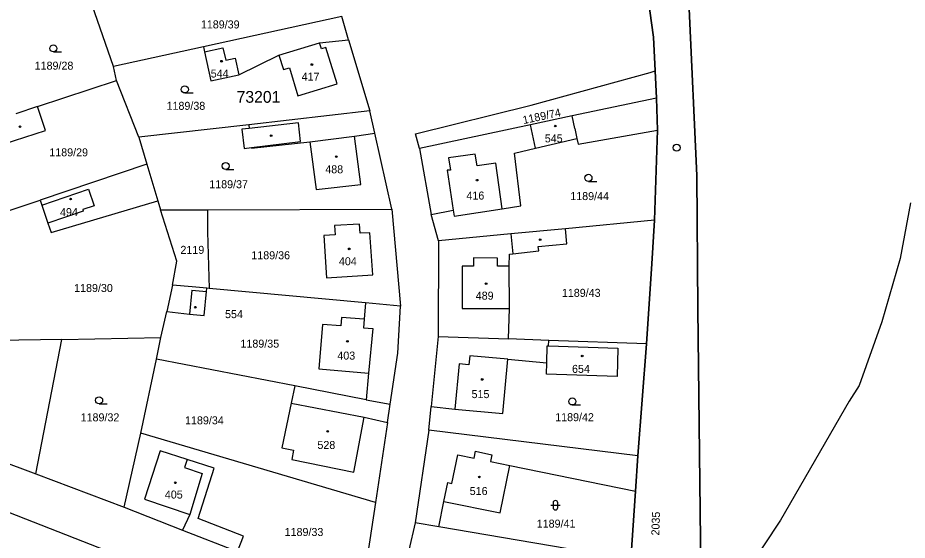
# Model space of a CAD drawing. Extents: x -794765 to -785424, y -1118958 to -1108731.
# Drawn here: x -787839.7 to -787650.9, y -1116620.6 to -1116509.6 of the extents above; entities that cross this region are included whole.
import ezdxf

# ---------------------------------------------------------------- set-up
doc = ezdxf.new("R2010")
doc.units = 0
for name, color, linetype in [('Level 66', 7, 'Continuous'), ('Level 75', 7, 'Continuous'), ('Level 76', 7, 'Continuous'), ('Level 77', 7, 'Continuous'), ('Level 79', 7, 'Continuous'), ('Level 81', 7, 'Continuous'), ('Vrstva 1', 7, 'Continuous'), ('Vrstva 55', 7, 'Continuous')]:
    doc.layers.add(name, color=color, linetype=linetype)

msp = doc.modelspace()

# ---------------------------------------------------------------- linework, layer by layer
at = {"layer": 'Level 66'}
for p, q in [((-787832.14, -1116516.88), (-787830.39, -1116516.88)), ((-787804.24, -1116525.6), (-787802.49, -1116525.6)), ((-787795.56, -1116541.86), (-787793.81, -1116541.86)), ((-787718.55, -1116544.38), (-787716.8, -1116544.38)), ((-787822.44, -1116591.63), (-787820.69, -1116591.63)), ((-787721.98, -1116591.87), (-787720.23, -1116591.87)), ((-787726.55, -1116613.16), (-787724.55, -1116613.16)), ((-787726.05, -1116612.66), (-787726.05, -1116613.66)), ((-787725.05, -1116613.66), (-787725.05, -1116612.66))]:
    msp.add_line(p, q, dxfattribs=at)
for centre in [(-787832.14, -1116516.13), (-787804.24, -1116524.85), (-787795.56, -1116541.11), (-787718.55, -1116543.63), (-787822.44, -1116590.88), (-787721.98, -1116591.12)]:
    msp.add_circle(centre, 0.75, dxfattribs=at)
for centre, start, end in [((-787725.55, -1116612.66), 0, 180), ((-787725.55, -1116613.66), 180, 359.9879)]:
    msp.add_arc(centre, 0.5, start, end, dxfattribs=at)
at = {"layer": 'Level 75'}
for p, q in [((-787819.38, -1116520), (-787824.68, -1116504.6)), ((-787770.94, -1116509.39), (-787800.27, -1116515.81)), ((-787769.46, -1116514.31), (-787770.94, -1116509.39)), ((-787769.46, -1116514.31), (-787764.94, -1116529.41)), ((-787800.27, -1116515.81), (-787819.38, -1116520)), ((-787800.27, -1116515.81), (-787800.05, -1116516.84)), ((-787818.75, -1116522.97), (-787819.38, -1116520)), ((-787705.48, -1116521.22), (-787704.38, -1116520.92)), ((-787704.38, -1116520.92), (-787704.1, -1116526.68)), ((-787835.52, -1116528.5), (-787818.75, -1116522.97)), ((-787814.01, -1116535.01), (-787818.75, -1116522.97)), ((-787704.1, -1116526.68), (-787703.91, -1116533.48)), ((-787835.52, -1116528.5), (-787840.15, -1116530.03)), ((-787764.94, -1116529.41), (-787790.66, -1116532.35)), ((-787763.9, -1116534.13), (-787764.94, -1116529.41)), ((-787790.66, -1116532.35), (-787814.01, -1116535.01)), ((-787730.84, -1116532.35), (-787754.45, -1116537.36)), ((-787729.78, -1116537.32), (-787730.84, -1116532.35)), ((-787760.31, -1116550.28), (-787763.9, -1116534.13)), ((-787754.45, -1116537.36), (-787755.27, -1116534.26)), ((-787703.91, -1116533.48), (-787704.56, -1116552.61)), ((-787814.01, -1116535.01), (-787812.3, -1116540.72)), ((-787754.45, -1116537.36), (-787751.94, -1116551.42)), ((-787812.3, -1116540.72), (-787834.94, -1116548.37)), ((-787812.3, -1116540.72), (-787809.97, -1116548.49)), ((-787842.6, -1116550.95), (-787834.94, -1116548.37)), ((-787809.97, -1116548.49), (-787809.38, -1116550.45)), ((-787809.38, -1116550.45), (-787799.45, -1116550.42)), ((-787799.45, -1116550.42), (-787760.31, -1116550.28)), ((-787760.31, -1116550.28), (-787758.43, -1116570.89)), ((-787750.4, -1116557.03), (-787751.94, -1116551.42)), ((-787704.56, -1116552.61), (-787723.43, -1116554.43)), ((-787750.4, -1116557.03), (-787750.49, -1116577.34)), ((-787806.86, -1116566.41), (-787808.09, -1116572.02)), ((-787799.07, -1116567.13), (-787799.56, -1116567.08)), ((-787765.88, -1116570.2), (-787799.07, -1116567.13)), ((-787758.43, -1116570.89), (-787765.88, -1116570.2)), ((-787809.3, -1116577.54), (-787808.09, -1116572.02)), ((-787830.33, -1116577.93), (-787809.3, -1116577.54)), ((-787810.27, -1116582.17), (-787809.3, -1116577.54)), ((-787750.49, -1116577.34), (-787751.96, -1116592.22)), ((-787750.49, -1116577.34), (-787735.49, -1116577.85)), ((-787830.33, -1116577.93), (-787859.23, -1116578.48)), ((-787835.9, -1116606.5), (-787830.33, -1116577.93)), ((-787726.99, -1116578.15), (-787735.49, -1116577.85)), ((-787727.03, -1116579.29), (-787726.99, -1116578.15)), ((-787706.23, -1116578.86), (-787726.99, -1116578.15)), ((-787706.23, -1116578.86), (-787708.05, -1116602.7)), ((-787813.56, -1116597.87), (-787810.27, -1116582.17)), ((-787780.89, -1116587.83), (-787810.27, -1116582.17)), ((-787765.71, -1116590.76), (-787780.89, -1116587.83)), ((-787765.71, -1116590.76), (-787760.64, -1116591.73)), ((-787761.22, -1116595.59), (-787760.64, -1116591.73)), ((-787752.45, -1116597.2), (-787751.96, -1116592.22)), ((-787761.22, -1116595.59), (-787763.76, -1116612.56)), ((-787860.7, -1116597.13), (-787835.9, -1116606.5)), ((-787817.13, -1116613.58), (-787813.56, -1116597.87)), ((-787763.76, -1116612.56), (-787813.56, -1116597.87)), ((-787752.45, -1116597.2), (-787755.32, -1116616.93)), ((-787708.05, -1116602.7), (-787752.45, -1116597.2)), ((-787708.05, -1116602.7), (-787708.57, -1116610.15)), ((-787835.9, -1116606.5), (-787817.13, -1116613.58)), ((-787708.57, -1116610.15), (-787709.58, -1116624.69)), ((-787817.13, -1116613.58), (-787804.7, -1116618.43)), ((-787813.81, -1116625.56), (-787841.59, -1116614.67)), ((-787755.32, -1116616.93), (-787756.71, -1116622.71)), ((-787750.28, -1116617.78), (-787755.32, -1116616.93)), ((-787804.7, -1116618.43), (-787793.06, -1116622.97)), ((-787709.58, -1116624.69), (-787750.28, -1116617.78))]:
    msp.add_line(p, q, dxfattribs=at)
for points in [[(-787693.98, -1116663.52), (-787691.68, -1116661.08), (-787693.44, -1116656.57), (-787695.13, -1116646.88), (-787694.77, -1116620.61), (-787695.36, -1116571.42), (-787695.53, -1116543.16), (-787697.17, -1116507.73), (-787699.35, -1116491.37), (-787704.1, -1116471.95), (-787713.77, -1116444.97), (-787730.07, -1116413.4), (-787748.85, -1116386.9), (-787769.63, -1116365.02), (-787796.66, -1116346.09)], [(-787809.33, -1116349.7), (-787801.57, -1116354.26), (-787773.08, -1116375.71), (-787754.69, -1116394.98), (-787740.05, -1116414.46), (-787723.7, -1116441.75), (-787713.22, -1116470.7), (-787707.44, -1116494.38), (-787704.74, -1116513.73), (-787704.38, -1116520.92)], [(-787792.79, -1116521.76), (-787784.26, -1116517.54), (-787783.32, -1116520.65), (-787782.02, -1116520.26), (-787780.23, -1116526.19), (-787771.91, -1116523.69), (-787774.28, -1116515.93), (-787775.23, -1116516.22), (-787775.62, -1116514.93), (-787769.46, -1116514.31)], [(-787800.05, -1116516.84), (-787796.14, -1116515.98), (-787795.55, -1116518.64), (-787793.57, -1116518.2), (-787792.79, -1116521.76)], [(-787800.05, -1116516.84), (-787798.69, -1116523.02), (-787792.79, -1116521.76)], [(-787755.27, -1116534.26), (-787730.74, -1116528.21), (-787705.48, -1116521.22)], [(-787704.1, -1116526.68), (-787722.02, -1116530.48), (-787730.84, -1116532.35)], [(-787844.57, -1116551.62), (-787845.98, -1116547.55), (-787848.96, -1116538.74), (-787842.56, -1116536.39), (-787833.85, -1116533.56), (-787835.52, -1116528.5)], [(-787790.66, -1116532.35), (-787790.57, -1116533.12), (-787792.14, -1116533.29), (-787791.67, -1116537.39), (-787790.11, -1116537.21), (-787790.09, -1116537.35), (-787777.71, -1116535.98), (-787776.37, -1116546.13), (-787766.9, -1116545.04), (-787768.19, -1116534.8), (-787763.9, -1116534.13)], [(-787729.78, -1116537.32), (-787721.01, -1116535.26), (-787720.75, -1116536.47), (-787703.91, -1116533.48)], [(-787751.94, -1116551.42), (-787747.28, -1116550.47), (-787747.09, -1116551.78), (-787736.85, -1116550.2), (-787732.87, -1116549.58), (-787734.24, -1116538.36), (-787729.78, -1116537.32)], [(-787834.94, -1116548.37), (-787834.59, -1116549.42), (-787833.29, -1116553.25), (-787832.62, -1116555.23), (-787809.97, -1116548.49)], [(-787806.86, -1116566.41), (-787805.96, -1116561.31), (-787809.38, -1116550.45)], [(-787799.45, -1116550.42), (-787799.44, -1116551.72), (-787799.43, -1116555.12), (-787799.07, -1116567.13)], [(-787704.56, -1116552.61), (-787705.09, -1116561.9), (-787706.23, -1116578.86)], [(-787764.34, -1116564.26), (-787764.96, -1116555.28), (-787767.04, -1116555.41), (-787767.16, -1116553.44), (-787772.47, -1116553.72), (-787772.34, -1116555.7), (-787774.72, -1116555.86), (-787774.14, -1116564.87), (-787764.34, -1116564.26)], [(-787723.43, -1116554.43), (-787735.01, -1116555.55), (-787750.4, -1116557.03)], [(-787735.49, -1116577.85), (-787735.33, -1116571.39), (-787735.39, -1116562.39), (-787735.34, -1116559.83), (-787734.61, -1116559.75), (-787729.11, -1116559.14), (-787729.2, -1116558.2), (-787723.12, -1116557.61), (-787723.43, -1116554.43)], [(-787799.56, -1116567.08), (-787802.69, -1116566.8), (-787806.86, -1116566.41)], [(-787808.09, -1116572.02), (-787803.23, -1116572.59), (-787800.1, -1116572.86), (-787799.63, -1116567.76), (-787799.56, -1116567.08)], [(-787765.88, -1116570.2), (-787766.18, -1116573.66), (-787770.99, -1116573.27), (-787771.15, -1116575.07), (-787775, -1116574.77), (-787775.78, -1116584.21), (-787765.23, -1116585.13), (-787765.71, -1116590.76)], [(-787760.64, -1116591.73), (-787759.04, -1116580.87), (-787758.43, -1116570.89)], [(-787727.03, -1116579.29), (-787712.3, -1116579.8), (-787712.46, -1116585.85), (-787727.48, -1116585.32), (-787727.4, -1116582.93)], [(-787727.4, -1116582.93), (-787727.28, -1116579.29), (-787727.03, -1116579.29)], [(-787751.96, -1116592.22), (-787746.92, -1116592.74), (-787736.74, -1116593.67), (-787735.66, -1116582.13), (-787727.4, -1116582.93)], [(-787780.89, -1116587.83), (-787781.67, -1116591.48), (-787783.63, -1116600.98), (-787781.17, -1116601.44), (-787781.55, -1116603.47), (-787768.37, -1116606.13), (-787766.18, -1116594.49), (-787761.22, -1116595.59)], [(-787793.06, -1116622.97), (-787791.76, -1116619.74), (-787801.44, -1116615.95), (-787798.01, -1116605.31), (-787803.77, -1116603.44), (-787809.5, -1116601.59), (-787812.82, -1116611.87), (-787803.19, -1116615.15), (-787804.7, -1116618.43)], [(-787750.28, -1116617.78), (-787749.25, -1116612.35), (-787737.26, -1116614.78), (-787735.22, -1116604.69), (-787708.57, -1116610.15)], [(-787763.76, -1116612.56), (-787766.31, -1116629.36), (-787768.64, -1116631.43), (-787771.78, -1116631.26)]]:
    msp.add_lwpolyline(points, dxfattribs=at)
at = {"layer": 'Level 77'}
for p, q in [((-787784.26, -1116517.54), (-787775.62, -1116514.93)), ((-787721.46, -1116533.12), (-787722.02, -1116530.48)), ((-787780.12, -1116531.94), (-787790.57, -1116533.12)), ((-787779.66, -1116535.91), (-787780.12, -1116531.94)), ((-787721.46, -1116533.12), (-787721.01, -1116535.26)), ((-787790.11, -1116537.21), (-787779.66, -1116535.91)), ((-787777.71, -1116535.98), (-787768.19, -1116534.8)), ((-787742.63, -1116538.57), (-787748.25, -1116539.4)), ((-787748.25, -1116539.4), (-787747.86, -1116541.97)), ((-787742.21, -1116541.11), (-787742.63, -1116538.57)), ((-787738.19, -1116540.51), (-787742.21, -1116541.11)), ((-787736.85, -1116550.2), (-787738.19, -1116540.51)), ((-787747.86, -1116541.97), (-787748.53, -1116542.01)), ((-787748.53, -1116542.01), (-787747.28, -1116550.47)), ((-787834.59, -1116549.42), (-787824.69, -1116546.01)), ((-787824.69, -1116546.01), (-787823.49, -1116549.55)), ((-787825.79, -1116550.69), (-787833.29, -1116553.25)), ((-787823.49, -1116549.55), (-787825.9, -1116550.36)), ((-787825.9, -1116550.36), (-787825.79, -1116550.69)), ((-787735.01, -1116555.55), (-787734.61, -1116559.75)), ((-787742.94, -1116560.59), (-787742.96, -1116562.36)), ((-787737.86, -1116560.66), (-787742.94, -1116560.59)), ((-787737.88, -1116562.37), (-787737.86, -1116560.66)), ((-787742.96, -1116562.36), (-787745.35, -1116562.41)), ((-787745.35, -1116562.41), (-787745.35, -1116571.36)), ((-787735.39, -1116562.39), (-787737.88, -1116562.37)), ((-787802.75, -1116567.47), (-787803.23, -1116572.59)), ((-787802.75, -1116567.47), (-787799.63, -1116567.76)), ((-787745.35, -1116571.36), (-787735.33, -1116571.39)), ((-787766.18, -1116573.66), (-787766.34, -1116575.49)), ((-787766.34, -1116575.49), (-787764.32, -1116575.62)), ((-787764.32, -1116575.62), (-787765.23, -1116585.13)), ((-787743.75, -1116581.41), (-787743.93, -1116583.35)), ((-787735.66, -1116582.13), (-787743.75, -1116581.41)), ((-787746.02, -1116583.14), (-787746.92, -1116592.74)), ((-787743.93, -1116583.35), (-787746.02, -1116583.14)), ((-787781.67, -1116591.48), (-787766.18, -1116594.49)), ((-787742.81, -1116603.14), (-787742.52, -1116601.71)), ((-787742.52, -1116601.71), (-787739.03, -1116602.47)), ((-787803.77, -1116603.44), (-787804.33, -1116605.18)), ((-787747.54, -1116608.51), (-787746.3, -1116602.44)), ((-787746.3, -1116602.44), (-787742.81, -1116603.14)), ((-787739.03, -1116602.47), (-787739.31, -1116603.86)), ((-787739.31, -1116603.86), (-787735.22, -1116604.69)), ((-787804.33, -1116605.18), (-787800.58, -1116606.41)), ((-787800.58, -1116606.41), (-787803.19, -1116615.15)), ((-787749.25, -1116612.35), (-787748.43, -1116608.33)), ((-787748.43, -1116608.33), (-787747.54, -1116608.51))]:
    msp.add_line(p, q, dxfattribs=at)
at = {"layer": 'Level 79'}
for centre in [(-787796.44, -1116518.86), (-787777.27, -1116519.56), (-787725.59, -1116532.63), (-787839.23, -1116532.76), (-787785.91, -1116534.66), (-787772.08, -1116539.12), (-787742.19, -1116544.12), (-787828.48, -1116548.13), (-787728.8, -1116556.74), (-787769.34, -1116558.72), (-787740.27, -1116566.11), (-787802.02, -1116571.11), (-787769.71, -1116578.35), (-787719.87, -1116581.45), (-787741.1, -1116586.44), (-787773.91, -1116597.47), (-787741.7, -1116607.16), (-787806.27, -1116608.4)]:
    msp.add_circle(centre, 0.175, dxfattribs=at)
at = {"layer": 'Level 81'}
msp.add_lwpolyline([(-787650.19, -1116548.91), (-787652.39, -1116560.73), (-787656.3, -1116574.23), (-787661.06, -1116587.72), (-787663.2, -1116591.08), (-787677.78, -1116616.32), (-787688.91, -1116633.13), (-787692.34, -1116638.18), (-787695.11, -1116645.4), (-787696.22, -1116648.29), (-787697.58, -1116660.12), (-787694.14, -1116669.61), (-787693.43, -1116671.58)], dxfattribs=at)
at = {"layer": 'Vrstva 1'}
msp.add_circle((-787699.82, -1116537.22), 0.75, dxfattribs=at)
at = {"layer": 'Vrstva 55'}
for points in [[(-787699.35, -1116491.37), (-787697.17, -1116507.73), (-787695.53, -1116543.16), (-787695.36, -1116571.42), (-787694.77, -1116620.61), (-787695.13, -1116646.88), (-787693.44, -1116656.57), (-787691.68, -1116661.08), (-787693.98, -1116663.52), (-787694.14, -1116669.51), (-787694.47, -1116681.92), (-787692.19, -1116731.59), (-787692.06, -1116734.36), (-787686.63, -1116766.25), (-787678.51, -1116793.87), (-787663.57, -1116829.76), (-787646.12, -1116860.74), (-787626.1, -1116888.93), (-787601.65, -1116916.45), (-787576.19, -1116941.14), (-787514.87, -1116995.01), (-787496.65, -1117010.38), (-787458.26, -1117042.74)], [(-787628.62, -1116907.25), (-787653.7, -1116872.34), (-787674.36, -1116833.72), (-787685.49, -1116804.26), (-787699.48, -1116766.3), (-787707.44, -1116735.64), (-787710.11, -1116725.38), (-787711.8, -1116696.13), (-787713, -1116663.97), (-787711.9, -1116654.76), (-787709.96, -1116629.67), (-787709.58, -1116624.69), (-787708.57, -1116610.15), (-787708.05, -1116602.7), (-787706.23, -1116578.86), (-787705.09, -1116561.9), (-787704.56, -1116552.61), (-787703.91, -1116533.48), (-787704.1, -1116526.68), (-787704.38, -1116520.92), (-787704.74, -1116513.73), (-787707.44, -1116494.38)]]:
    msp.add_lwpolyline(points, dxfattribs=at)

# ---------------------------------------------------------------- texts
at = {"layer": 'Level 76'}
for s, p in [('1189/39', (-787800.83, -1116511.89)), ('1189/28', (-787836.12, -1116520.65)), ('544', (-787798.74, -1116522.32)), ('417', (-787779.45, -1116522.99)), ('1189/38', (-787808.12, -1116529.18)), ('545', (-787727.82, -1116536.1)), ('1189/29', (-787833.01, -1116539.06)), ('488', (-787774.42, -1116542.66)), ('1189/37', (-787799.05, -1116545.83)), ('416', (-787744.45, -1116548.24)), ('1189/44', (-787722.41, -1116548.35)), ('494', (-787830.74, -1116551.76)), ('2119', (-787805.17, -1116559.77)), ('1189/36', (-787790.12, -1116560.92)), ('404', (-787771.53, -1116562.19)), ('1189/30', (-787827.74, -1116567.87)), ('489', (-787742.48, -1116569.5)), ('1189/43', (-787724.19, -1116568.9)), ('554', (-787795.7, -1116573.42)), ('1189/35', (-787792.43, -1116579.69)), ('403', (-787771.86, -1116582.23)), ('654', (-787722.04, -1116585.05)), ('515', (-787743.37, -1116590.41)), ('1189/32', (-787826.36, -1116595.35)), ('1189/34', (-787804.19, -1116595.98)), ('1189/42', (-787725.61, -1116595.31)), ('528', (-787776.09, -1116601.21)), ('516', (-787743.76, -1116610.99)), ('405', (-787808.48, -1116611.74)), ('1189/41', (-787729.53, -1116617.92)), ('1189/33', (-787783.05, -1116619.69))]:
    msp.add_text(s, height=1.7, dxfattribs=at).set_placement(p)
for s, rotation, p in [('1189/74', 12, (-787732.33, -1116532.22)), ('2035', 88, (-787703.52, -1116619.61))]:
    msp.add_text(s, height=1.7, rotation=rotation, dxfattribs=at).set_placement(p)
at = {"layer": 'Level 81'}
msp.add_text('73201', height=2.5, dxfattribs=at).set_placement((-787793.25, -1116527.68))

doc.saveas('drawing.dxf')
